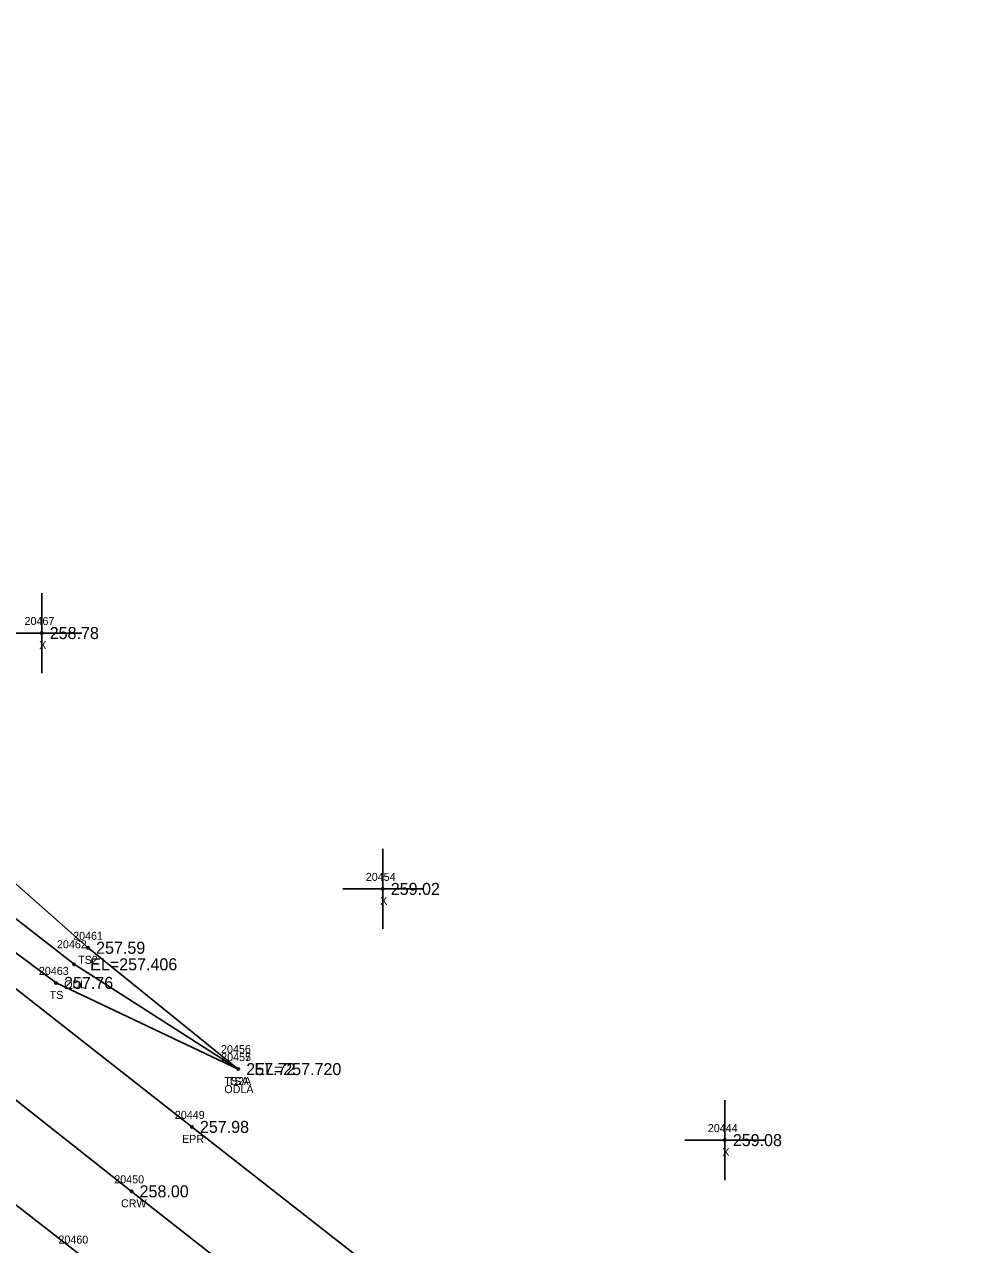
# Model space of a CAD drawing. Extents: x 1961330 to 1962287, y 800294 to 801079.
# Drawn here: x 1961532 to 1961649, y 800892.8 to 801045.3 of the extents above; entities that cross this region are included whole.
import ezdxf

# ---------------------------------------------------------------- set-up
doc = ezdxf.new("R2010")
doc.units = 0
for name, color, linetype in [('RD_DTM_BkLn1', 7, 'Continuous'), ('RD_DTM_BkLn2', 7, 'Continuous'), ('RD_DTM_BkLn_txCode', 7, 'Continuous'), ('RD_EX_H2O', 7, 'Continuous'), ('RD_EX_H2O_txCode', 7, 'Continuous'), ('RD_EX_Misc', 7, 'Continuous'), ('RD_EX_Misc_txCode', 7, 'Continuous'), ('RD_EX_Road', 7, 'Continuous'), ('RD_EX_Road_txCode', 7, 'Continuous'), ('RD_EX_TX_H2O_ELEV', 7, 'Continuous'), ('RD_EX_TX_Misc_ELEV', 7, 'Continuous'), ('RD_EX_TX_Road_ELEV', 7, 'Continuous'), ('RD_HC_Survey_ELEV', 7, 'Continuous'), ('RD_HC_Survey_txCode', 7, 'Continuous'), ('RD_SMD_Locator', 7, 'Continuous')]:
    doc.layers.add(name, color=color, linetype=linetype)

msp = doc.modelspace()

# ---------------------------------------------------------------- linework, layer by layer
at = {"layer": 'RD_DTM_BkLn1'}
msp.add_lwpolyline([(1962257.08, 800334.72), (1962203.79, 800372.43), (1962164.31, 800399.58), (1962126.58, 800429.85), (1962084.5, 800463.37), (1962045.12, 800502.48), (1962010.49, 800530.36), (1961971.27, 800562.01), (1961931.18, 800594.14), (1961890.91, 800625.98), (1961844.41, 800662.62), (1961808.07, 800691.13), (1961729.11, 800753.37), (1961696.19, 800780.32), (1961667.25, 800802.66), (1961624.93, 800836.78), (1961588.01, 800866), (1961545.37, 800899.49), (1961472.25, 800957.29), (1961437.91, 800983.99), (1961399.03, 801013.16), (1961365.01, 801035.89)], dxfattribs=at)
at = {"layer": 'RD_DTM_BkLn2'}
for points in [[(1961558.68, 800914.76), (1961539.94, 800929.91), (1961517.35, 800949.87), (1961506.13, 800959.13), (1961502.47, 800960.64), (1961500.68, 800958.21), (1961501.67, 800953.62)], [(1961558.68, 800914.76), (1961535.94, 800925.53), (1961512.88, 800942.67), (1961501.67, 800953.62)]]:
    msp.add_lwpolyline(points, dxfattribs=at)
at = {"layer": 'RD_EX_H2O'}
msp.add_lwpolyline([(1961558.68, 800914.76), (1961538.2, 800927.85), (1961514.97, 800945.92), (1961502.6, 800956.35)], dxfattribs=at)
at = {"layer": 'RD_EX_Misc'}
for p, q in [((1961534.15, 800964.23), (1961534.15, 800974.23)), ((1961529.15, 800969.23), (1961539.15, 800969.23)), ((1961576.73, 800932.27), (1961576.73, 800942.27)), ((1961571.73, 800937.27), (1961581.73, 800937.27)), ((1961619.43, 800900.89), (1961619.43, 800910.89)), ((1961614.43, 800905.89), (1961624.43, 800905.89))]:
    msp.add_line(p, q, dxfattribs=at)
at = {"layer": 'RD_EX_Road'}
for points in [[(1961651.45, 800830.73), (1961641.14, 800839.02), (1961595.18, 800874.45), (1961552.9, 800907.54), (1961510.92, 800940.49), (1961504.01, 800946.58), (1961476.53, 800968.16), (1961444.88, 800992.72), (1961406.41, 801021.23), (1961370.69, 801045.26)], [(1961660.52, 800795.31), (1961637.49, 800813.67), (1961617.86, 800829), (1961581.48, 800857.91), (1961538.42, 800891.96), (1961505, 800917.96), (1961467.33, 800947.97), (1961432.02, 800975.33), (1961392.71, 801004.33), (1961360.06, 801026.78)]]:
    msp.add_lwpolyline(points, dxfattribs=at)
at = {"layer": 'RD_SMD_Locator'}
for centre in [(1961534.15, 800969.23), (1961576.73, 800937.27), (1961539.94, 800929.91), (1961538.2, 800927.85), (1961535.94, 800925.53), (1961558.68, 800914.76), (1961558.68, 800914.76), (1961558.68, 800914.76), (1961552.9, 800907.54), (1961619.43, 800905.89), (1961545.37, 800899.49)]:
    msp.add_circle(centre, 0.15, dxfattribs=at)

# ---------------------------------------------------------------- texts
at = {"layer": 'RD_DTM_BkLn_txCode'}
for s, p in [('20461', (1961538.08, 800930.91)), ('TS2', (1961538.7, 800927.91)), ('20463', (1961533.8, 800926.53)), ('TS', (1961535.15, 800923.53)), ('20455', (1961556.56, 800915.76)), ('20457', (1961556.56, 800915.76)), ('TS2A', (1961556.95, 800912.76)), ('TSA', (1961557.39, 800912.76))]:
    msp.add_text(s, height=1, dxfattribs=at).set_placement(p)
at = {"layer": 'RD_EX_H2O_txCode'}
for s, p in [('20462', (1961536.06, 800929.85)), ('ODL', (1961536.96, 800924.85)), ('20456', (1961556.54, 800916.76)), ('ODLA', (1961556.95, 800911.76))]:
    msp.add_text(s, height=1, dxfattribs=at).set_placement(p)
at = {"layer": 'RD_EX_Misc_txCode'}
for s, p in [('20467', (1961532.01, 800970.23)), ('X', (1961533.84, 800967.23)), ('20454', (1961574.61, 800938.27)), ('X', (1961576.41, 800935.27)), ('20444', (1961617.31, 800906.89)), ('X', (1961619.12, 800903.89))]:
    msp.add_text(s, height=1, dxfattribs=at).set_placement(p)
at = {"layer": 'RD_EX_Road_txCode'}
for s, p in [('20449', (1961550.78, 800908.54)), ('EPR', (1961551.67, 800905.54)), ('20460', (1961536.24, 800892.96))]:
    msp.add_text(s, height=1, dxfattribs=at).set_placement(p)
at = {"layer": 'RD_EX_TX_H2O_ELEV'}
for s, p in [('EL=257.406', (1961540.2, 800927.1)), ('EL=257.720', (1961560.68, 800914.01))]:
    msp.add_text(s, height=1.5, dxfattribs=at).set_placement(p)
at = {"layer": 'RD_EX_TX_Misc_ELEV'}
for s, p in [('258.78', (1961535.15, 800968.48)), ('259.02', (1961577.73, 800936.52)), ('257.59', (1961540.94, 800929.16)), ('257.76', (1961536.94, 800924.78)), ('257.72', (1961559.68, 800914.01)), ('257.72', (1961559.68, 800914.01)), ('259.08', (1961620.43, 800905.14))]:
    msp.add_text(s, height=1.5, dxfattribs=at).set_placement(p)
at = {"layer": 'RD_EX_TX_Road_ELEV'}
msp.add_text('257.98', height=1.5, dxfattribs=at).set_placement((1961553.9, 800906.79))
at = {"layer": 'RD_HC_Survey_ELEV'}
msp.add_text('258.00', height=1.5, dxfattribs=at).set_placement((1961546.37, 800898.74))
at = {"layer": 'RD_HC_Survey_txCode'}
for s, p in [('20450', (1961543.21, 800900.49)), ('CRW', (1961544.05, 800897.49))]:
    msp.add_text(s, height=1, dxfattribs=at).set_placement(p)

doc.saveas('drawing.dxf')
